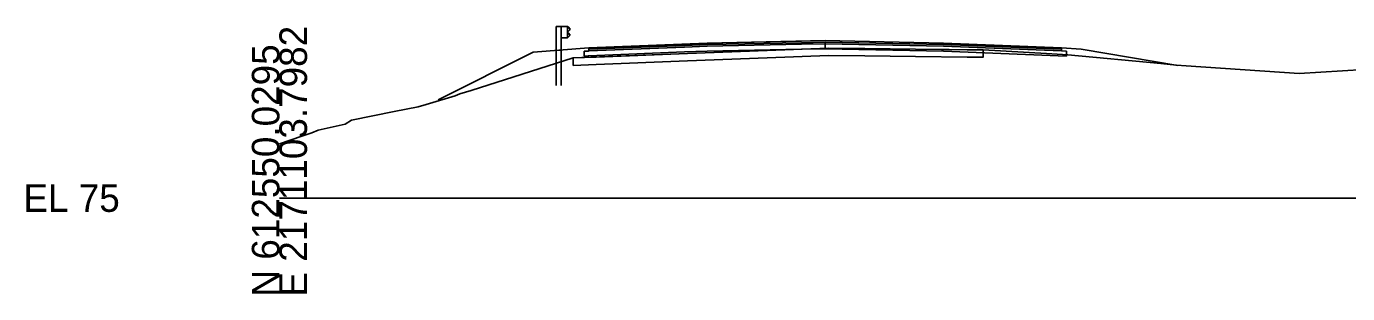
# Model space of a CAD drawing. Extents: x -26 to 1303, y -3010 to 12023.
# Drawn here: x -25.7 to 108.5, y 8490.3 to 8517.4 of the extents above; entities that cross this region are included whole.
import ezdxf

# ---------------------------------------------------------------- set-up
doc = ezdxf.new("R2010")
doc.units = 0
for name, color, linetype in [('RD_GPK_XS_Cell', 7, 'Continuous'), ('RD_PD_Final_TrvlWay', 7, 'Continuous'), ('RD_XS_Base', 7, 'Continuous'), ('RD_XS_ExGround', 7, 'Continuous'), ('RD_XS_ExPaveRet', 7, 'Continuous'), ('RD_XS_GR', 7, 'Continuous'), ('RD_XS_Greenside', 7, 'Continuous'), ('RD_XS_Pave', 7, 'Continuous'), ('RD_XS_PaveOvlay_CP', 7, 'Continuous'), ('RD_XS_TieSlope', 7, 'Continuous')]:
    doc.layers.add(name, color=color, linetype=linetype)

msp = doc.modelspace()

# ---------------------------------------------------------------- linework, layer by layer
at = {"layer": 'RD_GPK_XS_Cell'}
msp.add_line((0, 8500), (150, 8500), dxfattribs=at)
at = {"layer": 'RD_PD_Final_TrvlWay'}
msp.add_lwpolyline([(28.6, 8511.42), (28.6, 8515.03), (28.1, 8514.99), (28.1, 8511.42)], dxfattribs=at)
at = {"layer": 'RD_XS_Base'}
for p, q in [((41.12, 8515.33), (31.43, 8514.94)), ((43.43, 8515.42), (41.12, 8515.33)), ((53.03, 8515.61), (43.43, 8515.42)), ((55.43, 8515.66), (53.03, 8515.61)), ((55.43, 8515.78), (55.43, 8515.82)), ((55.43, 8515.82), (55.43, 8515.68)), ((55.43, 8515.66), (55.43, 8515.82)), ((55.43, 8515.82), (55.43, 8515.82)), ((55.43, 8515.82), (55.43, 8515.82)), ((55.43, 8515.82), (55.43, 8515.16)), ((55.43, 8515.66), (55.43, 8515.78)), ((55.43, 8515.68), (55.43, 8515.16)), ((55.43, 8515.56), (55.43, 8515.66)), ((55.43, 8515.16), (55.43, 8515.66)), ((55.43, 8515.66), (55.43, 8515.66)), ((55.43, 8515.66), (55.43, 8515.66)), ((55.43, 8515.66), (55.43, 8515.66)), ((67.43, 8515.42), (55.43, 8515.66)), ((55.43, 8515.16), (55.43, 8515.56)), ((79.43, 8514.94), (67.43, 8515.42)), ((69.43, 8515.34), (69.43, 8515.34)), ((31.34, 8514.93), (30.93, 8514.92)), ((30.93, 8514.92), (30.93, 8514.82)), ((30.93, 8514.82), (30.93, 8514.42)), ((30.93, 8514.42), (31.34, 8514.43)), ((31.43, 8514.94), (31.34, 8514.93)), ((31.34, 8514.43), (31.43, 8514.44)), ((31.43, 8514.44), (41.12, 8514.83)), ((41.12, 8514.83), (43.43, 8514.92)), ((43.43, 8514.92), (53.03, 8515.11)), ((53.03, 8515.11), (55.43, 8515.16)), ((55.43, 8515.16), (55.43, 8515.16)), ((55.43, 8515.16), (55.43, 8515.16)), ((55.43, 8515.16), (67.43, 8514.92)), ((67.43, 8514.92), (79.93, 8514.42)), ((69.43, 8514.84), (69.43, 8514.84)), ((79.93, 8514.92), (79.43, 8514.94)), ((79.43, 8514.94), (79.43, 8514.94)), ((79.93, 8514.42), (79.93, 8514.92)), ((79.93, 8514.92), (79.93, 8514.92))]:
    msp.add_line(p, q, dxfattribs=at)
at = {"layer": 'RD_XS_ExGround'}
msp.add_lwpolyline([(0, 8505.52), (2.26, 8506.27), (3.3, 8506.61), (3.93, 8506.88), (6.67, 8507.5), (7.32, 8507.91), (11.64, 8508.78), (14.08, 8509.27), (14.91, 8509.51), (17.86, 8510.37), (18.32, 8510.59), (19.48, 8510.93), (29.84, 8514.22), (41.44, 8514.67), (55.77, 8515.23), (64.6, 8515.12), (71.46, 8515.04), (77.88, 8514.66), (80.07, 8514.54), (89.5, 8513.65), (91.11, 8513.5), (92.08, 8513.43), (103.56, 8512.64), (114.55, 8513.31)], dxfattribs=at)
at = {"layer": 'RD_XS_ExPaveRet'}
for points in [[(69.85, 8515.06), (64.6, 8515.12), (59.46, 8515.18), (55.77, 8515.23), (49.53, 8514.98), (41.44, 8514.67), (32.18, 8514.31), (29.84, 8514.22), (29.84, 8514.22), (29.84, 8513.93), (29.84, 8513.47), (29.84, 8513.47), (32.18, 8513.56), (41.44, 8513.92), (49.53, 8514.23), (55.77, 8514.48), (59.46, 8514.43), (64.6, 8514.37), (69.85, 8514.31), (71.45, 8514.29), (71.45, 8514.71), (71.45, 8515.04), (69.85, 8515.06)], [(69.85, 8515.06), (64.6, 8515.12), (59.46, 8515.18), (55.77, 8515.23), (49.53, 8514.98), (41.44, 8514.67), (32.18, 8514.31), (29.84, 8514.22), (29.84, 8513.93), (29.84, 8513.47), (32.18, 8513.56), (41.44, 8513.92), (49.53, 8514.23), (55.77, 8514.48), (59.46, 8514.43), (64.6, 8514.37), (69.85, 8514.31), (71.45, 8514.29), (71.45, 8514.71), (71.45, 8515.04), (69.85, 8515.06)]]:
    msp.add_lwpolyline(points, dxfattribs=at)
at = {"layer": 'RD_XS_GR'}
for p, q in [((28.1, 8514.99), (28.1, 8517.42)), ((28.1, 8517.42), (28.35, 8517.42)), ((28.35, 8517.42), (28.6, 8517.42)), ((28.6, 8517.42), (28.6, 8515.03)), ((28.6, 8516.26), (28.6, 8517.42)), ((28.6, 8517.42), (29.26, 8517.42)), ((29.26, 8517.42), (29.26, 8516.26)), ((29.31, 8517.37), (29.26, 8517.42)), ((29.26, 8517.42), (29.26, 8517.21)), ((29.26, 8517.21), (29.26, 8516.26)), ((29.26, 8516.84), (29.48, 8517.08)), ((29.31, 8516.79), (29.26, 8516.84)), ((29.53, 8517.13), (29.31, 8517.37)), ((29.53, 8516.55), (29.31, 8516.79)), ((29.48, 8517.08), (29.53, 8517.13)), ((29.26, 8516.26), (28.6, 8516.26)), ((29.26, 8516.26), (29.48, 8516.49)), ((29.48, 8516.49), (29.53, 8516.55)), ((28.6, 8515.03), (28.1, 8514.99))]:
    msp.add_line(p, q, dxfattribs=at)
at = {"layer": 'RD_XS_Greenside'}
for p, q in [((25.78, 8514.8), (16.12, 8509.97)), ((81.43, 8515.1), (91.23, 8513.46))]:
    msp.add_line(p, q, dxfattribs=at)
at = {"layer": 'RD_XS_Pave'}
for p, q in [((41.12, 8515.64), (31.43, 8515.26)), ((41.12, 8515.48), (31.43, 8515.1)), ((31.43, 8515.1), (41.12, 8515.48)), ((31.43, 8514.94), (41.12, 8515.33)), ((43.43, 8515.74), (41.12, 8515.64)), ((43.43, 8515.58), (41.12, 8515.48)), ((41.12, 8515.48), (43.43, 8515.58)), ((41.12, 8515.33), (43.43, 8515.42)), ((53.03, 8515.93), (43.43, 8515.74)), ((53.03, 8515.77), (43.43, 8515.58)), ((43.43, 8515.58), (53.03, 8515.77)), ((43.43, 8515.42), (53.03, 8515.61)), ((55.43, 8515.98), (53.03, 8515.93)), ((55.43, 8515.82), (53.03, 8515.77)), ((53.03, 8515.77), (55.43, 8515.82)), ((53.03, 8515.61), (55.43, 8515.66)), ((67.43, 8515.74), (55.43, 8515.98)), ((55.43, 8515.98), (55.43, 8515.98)), ((55.43, 8515.98), (55.43, 8515.98)), ((55.43, 8515.78), (55.43, 8515.82)), ((55.43, 8515.82), (55.43, 8515.78)), ((55.43, 8515.66), (55.43, 8515.82)), ((55.43, 8515.82), (55.43, 8515.82)), ((55.43, 8515.82), (55.43, 8515.82)), ((55.43, 8515.82), (55.43, 8515.82)), ((55.43, 8515.82), (55.43, 8515.82)), ((55.43, 8515.82), (67.43, 8515.58)), ((67.43, 8515.58), (55.43, 8515.82)), ((55.43, 8515.82), (55.43, 8515.82)), ((55.43, 8515.82), (55.43, 8515.82)), ((55.43, 8515.82), (55.43, 8515.66)), ((55.43, 8515.66), (55.43, 8515.78)), ((55.43, 8515.78), (55.43, 8515.66)), ((55.43, 8515.66), (55.43, 8515.66)), ((55.43, 8515.66), (55.43, 8515.66)), ((55.43, 8515.66), (67.43, 8515.42)), ((79.43, 8515.26), (67.43, 8515.74)), ((67.43, 8515.58), (79.43, 8515.1)), ((79.43, 8515.1), (67.43, 8515.58)), ((67.43, 8515.42), (79.43, 8514.94)), ((69.43, 8515.66), (69.43, 8515.66)), ((69.43, 8515.5), (69.43, 8515.5)), ((69.43, 8515.5), (69.43, 8515.5)), ((69.43, 8515.34), (69.43, 8515.34)), ((31.43, 8515.26), (31.43, 8515.23)), ((31.43, 8515.23), (31.43, 8515.1)), ((31.43, 8515.1), (31.43, 8515.07)), ((31.43, 8515.07), (31.43, 8514.94)), ((79.43, 8515.1), (79.43, 8515.26)), ((79.43, 8515.26), (79.43, 8515.26)), ((79.43, 8514.94), (79.43, 8515.1)), ((79.43, 8515.1), (79.43, 8515.1))]:
    msp.add_line(p, q, dxfattribs=at)
at = {"layer": 'RD_XS_PaveOvlay_CP'}
for p, q in [((31.43, 8515.26), (43.43, 8515.74)), ((43.43, 8515.74), (55.43, 8515.98)), ((55.43, 8515.98), (67.43, 8515.74)), ((67.43, 8515.74), (79.43, 8515.26))]:
    msp.add_line(p, q, dxfattribs=at)
at = {"layer": 'RD_XS_TieSlope'}
for p, q in [((31.43, 8515.26), (25.78, 8514.8)), ((79.43, 8515.26), (81.43, 8515.1))]:
    msp.add_line(p, q, dxfattribs=at)

# ---------------------------------------------------------------- texts
at = {"layer": 'RD_GPK_XS_Cell'}
for s, p in [('E 2171103.7982', (2.8, 8490)), ('N 612550.0295', (0, 8490))]:
    msp.add_text(s, height=2.8, rotation=90, dxfattribs=at).set_placement(p)
msp.add_text('EL 75', height=2.8, dxfattribs=at).set_placement((-26, 8498.6))

doc.saveas('drawing.dxf')
